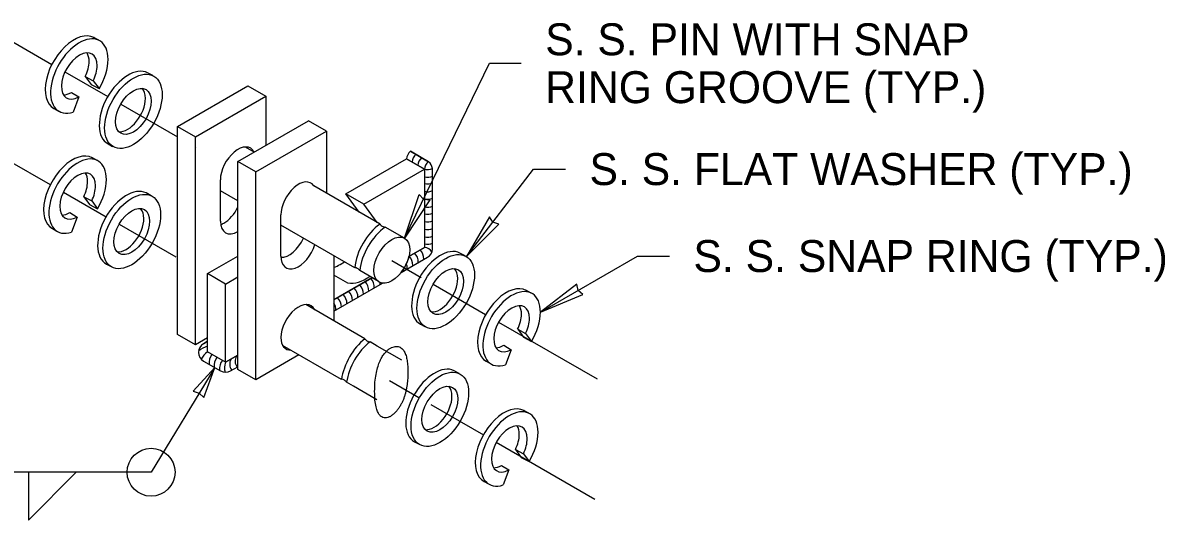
# Model space of a CAD drawing. Extents: x 99862 to 112891, y 95370 to 105076.
# Drawn here: x 101750 to 102323, y 104490 to 104740 of the extents above; entities that cross this region are included whole.
import ezdxf

# ---------------------------------------------------------------- set-up
doc = ezdxf.new("R2010")
doc.units = 0
for name, color, linetype in [('Level 15', 7, 'Continuous'), ('Level 20', 7, 'Continuous'), ('Level 7', 7, 'Continuous'), ('Level 8', 7, 'Continuous')]:
    doc.layers.add(name, color=color, linetype=linetype)

msp = doc.modelspace()

# ---------------------------------------------------------------- linework, layer by layer
at = {"layer": 'Level 15'}
for p, q in [((101743.24, 104731.17), (101764.8, 104718.73)), ((101771.33, 104714.96), (101792.78, 104702.59)), ((101941.54, 104631.62), (101984.05, 104719.3)), ((101984.05, 104719.3), (102000.05, 104719.3)), ((101799.28, 104698.83), (101827.68, 104682.45)), ((101836.69, 104677.25), (101836.95, 104677.1)), ((101742.43, 104670.96), (101763.99, 104658.52)), ((101972.63, 104622.37), (102006.26, 104666.25)), ((102006.26, 104666.25), (102022.26, 104666.25)), ((101770.53, 104654.75), (101791.97, 104642.38)), ((101798.48, 104638.62), (101826.87, 104622.24)), ((102009.65, 104594.55), (102058.36, 104622.68)), ((102058.36, 104622.68), (102074.36, 104622.68)), ((101935.1, 104620.47), (101949.9, 104611.93)), ((101955.84, 104608.51), (101982.19, 104593.31)), ((101988.7, 104589.55), (102038.07, 104561.07)), ((101846.48, 104566.78), (101814.49, 104514.33)), ((101933.96, 104560.25), (101948.76, 104551.72)), ((101954.69, 104548.29), (101981.05, 104533.09)), ((101987.55, 104529.33), (102036.92, 104500.85)), ((101814.49, 104514.33), (101691.48, 104514.33)), ((101753, 104514.33), (101753, 104490.33)), ((101753, 104490.33), (101777, 104514.33))]:
    msp.add_line(p, q, dxfattribs=at)
for points in [[(101941.54, 104631.62), (101948.81, 104653.46), (101951.04, 104651.21), (101954.18, 104650.86)], [(101972.63, 104622.37), (101988.89, 104638.67), (101985.88, 104639.65), (101984.15, 104642.3)], [(102009.65, 104594.55), (102030.91, 104603.38), (102028.51, 104605.44), (102027.93, 104608.55)], [(101846.48, 104566.78), (101835.66, 104554.96), (101838.67, 104553.97), (101840.93, 104551.75)]]:
    msp.add_lwpolyline(points, close=True, dxfattribs=at)
msp.add_circle((101814.49, 104514.33), 12, dxfattribs=at)
at = {"layer": 'Level 7'}
for p, q in [((101788.24, 104730.81), (101785.66, 104732.25)), ((101815.36, 104713.09), (101812.77, 104714.53)), ((101781.53, 104712.64), (101784.44, 104708.67)), ((101781.53, 104712.64), (101785.53, 104710.52)), ((101784.44, 104708.67), (101788.44, 104706.56)), ((101785.53, 104710.52), (101788.44, 104706.56)), ((101774.53, 104704.67), (101778.22, 104702.39)), ((101778.22, 104702.39), (101775.41, 104694.85)), ((101827.68, 104687.61), (101863.03, 104708.02)), ((101836.69, 104682.41), (101872.04, 104702.82)), ((101863.03, 104708.02), (101872.04, 104702.82)), ((101872.04, 104702.82), (101872.04, 104678.2)), ((101765.82, 104696.61), (101768.11, 104695.35)), ((101827.68, 104687.61), (101836.69, 104682.41)), ((101827.68, 104583.41), (101827.68, 104687.61)), ((101858.01, 104670.1), (101893.37, 104690.51)), ((101867.02, 104664.9), (101902.37, 104685.31)), ((101902.37, 104685.31), (101893.37, 104690.51)), ((101902.37, 104685.31), (101902.37, 104654.24)), ((101836.69, 104578.21), (101836.69, 104682.41)), ((101792.93, 104678.89), (101795.22, 104677.63)), ((101866.15, 104674.8), (101861.79, 104677.32)), ((101787.44, 104670.6), (101784.85, 104672.04)), ((101867.02, 104664.9), (101858.01, 104670.1)), ((101858.01, 104565.9), (101858.01, 104670.1)), ((101912.1, 104653.83), (101942.58, 104671.43)), ((101951.58, 104666.23), (101942.58, 104671.43)), ((101867.02, 104560.7), (101867.02, 104664.9)), ((101921.1, 104648.63), (101951.58, 104666.23)), ((101951.58, 104666.23), (101951.58, 104627.03)), ((101849.25, 104640.09), (101849.25, 104660.81)), ((101929.29, 104638.7), (101896.12, 104657.85)), ((101780.72, 104652.43), (101783.64, 104648.46)), ((101780.72, 104652.43), (101784.72, 104650.31)), ((101814.55, 104652.88), (101811.96, 104654.32)), ((101858.01, 104650.3), (101849.25, 104655.36)), ((101918.86, 104644.73), (101912.1, 104653.83)), ((101921.1, 104648.63), (101912.1, 104653.83)), ((101783.64, 104648.46), (101787.63, 104646.34)), ((101784.72, 104650.31), (101787.63, 104646.34)), ((101927.88, 104639.51), (101921.1, 104648.63)), ((101773.73, 104644.46), (101777.41, 104642.18)), ((101777.41, 104642.18), (101774.61, 104634.64)), ((101879.58, 104622.57), (101879.58, 104643.3)), ((101765.01, 104636.4), (101767.31, 104635.14)), ((101916.55, 104616.83), (101879.58, 104638.18)), ((101941.54, 104631.63), (101931.88, 104637.21)), ((101842.85, 104613.85), (101858.01, 104622.6)), ((101906.1, 104622.87), (101906.1, 104590.18)), ((101943.76, 104622.51), (101951.58, 104627.03)), ((101971.91, 104622.76), (101969.33, 104624.2)), ((101792.12, 104618.68), (101794.42, 104617.42)), ((101909.32, 104618.5), (101911.49, 104619.76)), ((101842.85, 104574.65), (101842.85, 104613.85)), ((101851.85, 104608.65), (101842.85, 104613.85)), ((101851.85, 104608.65), (101858.01, 104612.2)), ((101913.04, 104609.17), (101906.1, 104613.18)), ((101906.1, 104600.77), (101925.24, 104611.82)), ((101928.31, 104610.04), (101919.1, 104615.36)), ((101851.85, 104569.45), (101851.85, 104608.65)), ((102004.96, 104604.14), (102002.37, 104605.57)), ((101921.69, 104581.18), (101892, 104598.32)), ((101949.49, 104588.56), (101951.78, 104587.3)), ((101836.69, 104578.21), (101827.68, 104583.41)), ((101998.25, 104585.96), (102001.16, 104582)), ((101998.25, 104585.96), (102002.24, 104583.85)), ((102002.24, 104583.85), (102005.16, 104579.88)), ((101842.85, 104581.76), (101836.69, 104578.21)), ((101909.93, 104560.88), (101880.45, 104577.9)), ((101927.89, 104577.6), (101924.27, 104579.69)), ((101940.13, 104570.54), (101927.89, 104577.6)), ((101991.25, 104578), (101994.93, 104575.72)), ((102001.16, 104582), (102005.16, 104579.88)), ((101851.85, 104569.45), (101842.85, 104574.65)), ((101851.85, 104569.45), (101858.01, 104573.01)), ((101888.62, 104573.17), (101867.02, 104560.7)), ((101994.93, 104575.72), (101992.13, 104568.18)), ((101867.02, 104560.7), (101858.01, 104565.9)), ((101969, 104563.79), (101966.41, 104565.22)), ((101982.53, 104569.94), (101984.83, 104568.68)), ((101915.94, 104557.41), (101912.48, 104559.41)), ((101927.68, 104550.63), (101915.94, 104557.41)), ((102003.82, 104543.92), (102001.23, 104545.36)), ((101946.57, 104529.59), (101948.86, 104528.33)), ((101997.1, 104525.74), (102000.01, 104521.78)), ((101997.1, 104525.74), (102001.1, 104523.63)), ((102000.01, 104521.78), (102004.01, 104519.66)), ((102001.1, 104523.63), (102004.01, 104519.66)), ((101990.11, 104517.78), (101993.79, 104515.5)), ((101993.79, 104515.5), (101990.99, 104507.96)), ((101981.39, 104509.72), (101983.68, 104508.46))]:
    msp.add_line(p, q, dxfattribs=at)
for centre, major_axis, ratio, start_param, end_param in [((101775.84, 104714.38), (10.2, 17.67), 0.57735, 6.163864, 9.44206), ((101778.51, 104712.9), (10.2, 17.67), 0.57735, 5.497787, 9.994128), ((101778.51, 104712.9), (6.34, 10.98), 0.57735, 5.497787, 10.177688), ((101774.5, 104715.01), (6.34, 10.98), 0.57735, 4.827845, 5.497787), ((101774.5, 104715.01), (6.34, 10.98), 0.57735, 5.497787, 5.991841), ((101778.51, 104712.9), (10.2, 17.67), 0.57735, 4.686514, 5.497787), ((101778.51, 104712.9), (6.34, 10.98), 0.57735, 4.826963, 5.497787), ((101802.95, 104696.66), (10.2, 17.67), 0.57735, 0.036728, 3.158875), ((101774.5, 104715.01), (6.34, 10.98), 0.57735, 3.478267, 3.930251), ((101802.72, 104696.53), (6.34, 10.98), 0.57735, 5.497787, 6.114666), ((101802.72, 104696.53), (6.34, 10.98), 0.57735, 3.412792, 5.497787), ((101775.03, 104654.17), (10.2, 17.67), 0.57735, 6.163864, 9.44206), ((101858.08, 104665.91), (6.25, 10.83), 0.57735, 5.924907, 8.63938), ((101777.7, 104652.69), (10.2, 17.67), 0.57735, 5.497787, 9.994128), ((101777.7, 104652.69), (6.34, 10.98), 0.57735, 5.497787, 10.177688), ((101773.7, 104654.79), (6.34, 10.98), 0.57735, 5.497787, 5.991841), ((101773.7, 104654.79), (6.34, 10.98), 0.57735, 4.827845, 5.497787), ((101777.7, 104652.69), (6.34, 10.98), 0.57735, 4.826963, 5.497787), ((101802.14, 104636.44), (10.2, 17.67), 0.57735, 0.036728, 3.158875), ((101777.7, 104652.69), (10.2, 17.67), 0.57735, 4.686514, 5.497787), ((101888.42, 104648.4), (-6.25, -10.83), 0.57735, 2.868315, 5.497787), ((101801.91, 104636.32), (6.34, 10.98), 0.57735, 5.497787, 6.114666), ((101851.01, 104649.39), (6.25, 10.83), 0.57735, 3.918713, 4.842037), ((101773.7, 104654.79), (6.34, 10.98), 0.57735, 3.478267, 3.930251), ((101801.91, 104636.32), (6.34, 10.98), 0.57735, 3.412792, 5.497787), ((101858.08, 104645.19), (6.25, 10.83), 0.57735, 2.356194, 3.918713), ((101851.01, 104649.39), (6.25, 10.83), 0.57735, 3.741522, 3.918713), ((101930.87, 104623.05), (10.2, 17.67), 0.57735, 0.895049, 2.233314), ((101933.41, 104621.53), (10.2, 17.67), 0.57735, 0.891866, 2.230172), ((101930.58, 104637.95), (1.29, -0.75), 0.229667, 3.141593, 6.096097), ((101888.42, 104627.68), (6.25, 10.83), 0.57735, 2.356194, 5.095834), ((101883.78, 104633.47), (6.25, 10.83), 0.57735, 3.432988, 4.871182), ((101959.51, 104606.33), (10.2, 17.67), 0.57735, 0.036728, 3.158875), ((101909.32, 104668.8), (-9.15, -52.25), 0.457456, 0.239539, 0.365772), ((101917.84, 104616.07), (1.28, -0.76), 0.229667, 0.326419, 3.141593), ((101922.05, 104661.45), (-9.15, -52.25), 0.457456, 0.006259, 0.445323), ((101959.28, 104606.2), (6.34, 10.98), 0.57735, 3.412792, 5.497787), ((101959.28, 104606.2), (6.34, 10.98), 0.57735, 5.497787, 6.114666), ((101992.56, 104587.7), (10.2, 17.67), 0.57735, 6.163864, 9.44206), ((101995.23, 104586.23), (10.2, 17.67), 0.57735, 5.497787, 9.994128), ((101995.23, 104586.23), (6.34, 10.98), 0.57735, 5.497787, 10.177688), ((101888.42, 104586.92), (-6.25, -10.83), 0.57735, 2.771879, 5.497787), ((101991.22, 104588.33), (6.34, 10.98), 0.57735, 5.497787, 5.991841), ((101995.23, 104586.23), (10.2, 17.67), 0.57735, 4.686514, 5.497787), ((101991.22, 104588.33), (6.34, 10.98), 0.57735, 4.827845, 5.497787), ((101995.23, 104586.23), (6.34, 10.98), 0.57735, 4.826963, 5.497787), ((101888.42, 104586.92), (-6.25, -10.83), 0.57735, 5.497787, 6.617535), ((101924.14, 104566.19), (10.2, 17.67), 0.57735, 0.956158, 2.18156), ((101926.68, 104564.66), (10.2, 17.67), 0.57735, 0.953119, 2.178536), ((101922.98, 104580.44), (1.29, -0.75), 0.229667, 3.141593, 6.096097), ((101991.22, 104588.33), (6.34, 10.98), 0.57735, 3.478267, 3.930251), ((101956.59, 104547.35), (10.2, 17.67), 0.57735, 0.036728, 3.158875), ((101911.2, 104560.17), (1.28, -0.76), 0.229667, 6.283185, 9.424778), ((101956.36, 104547.22), (6.34, 10.98), 0.57735, 5.497787, 6.114666), ((101956.36, 104547.22), (6.34, 10.98), 0.57735, 3.412792, 5.497787), ((101991.41, 104527.48), (10.2, 17.67), 0.57735, 6.163864, 9.44206), ((101994.08, 104526.01), (10.2, 17.67), 0.57735, 5.497787, 9.994128), ((101994.08, 104526.01), (6.34, 10.98), 0.57735, 5.497787, 10.177688), ((101990.08, 104528.11), (6.34, 10.98), 0.57735, 5.497787, 5.991841), ((101990.08, 104528.11), (6.34, 10.98), 0.57735, 4.827845, 5.497787), ((101994.08, 104526.01), (6.34, 10.98), 0.57735, 4.826963, 5.497787), ((101994.08, 104526.01), (10.2, 17.67), 0.57735, 4.686514, 5.497787), ((101990.08, 104528.11), (6.34, 10.98), 0.57735, 3.478267, 3.930251)]:
    msp.add_ellipse(centre, major_axis=major_axis, ratio=ratio, start_param=start_param, end_param=end_param, dxfattribs=at)
for centre, major_axis in [((101805.62, 104695.18), (10.2, 17.67)), ((101805.62, 104695.18), (6.34, 10.98)), ((101804.81, 104634.97), (10.2, 17.67)), ((101804.81, 104634.97), (6.34, 10.98)), ((101935.2, 104620.64), (6.34, 10.98)), ((101962.18, 104604.85), (10.2, 17.67)), ((101962.18, 104604.85), (6.34, 10.98)), ((101959.26, 104545.88), (10.2, 17.67)), ((101959.26, 104545.88), (6.34, 10.98))]:
    msp.add_ellipse(centre, major_axis=major_axis, ratio=0.57735, dxfattribs=at)
msp.add_open_spline([(101926.55, 104554.86), (101926.55, 104535.27), (101943.52, 104545.06), (101943.52, 104564.66), (101943.52, 104584.26), (101926.55, 104574.46), (101926.55, 104554.86)], degree=4, dxfattribs=at)
at = {"layer": 'Level 8'}
for p, q in [((101944.48, 104675.21), (101953.58, 104669.88)), ((101944.48, 104675.21), (101953.58, 104669.88)), ((101955.55, 104626.13), (101955.55, 104666.62)), ((101955.55, 104626.13), (101955.55, 104666.62)), ((101939.85, 104614.49), (101953.06, 104622.11)), ((101939.85, 104614.49), (101953.06, 104622.11)), ((101906.1, 104595), (101930.54, 104609.11)), ((101906.1, 104595), (101930.54, 104609.11)), ((101840.76, 104578.74), (101842.85, 104579.94)), ((101840.76, 104578.74), (101842.85, 104579.94)), ((101840.76, 104570.08), (101849.35, 104565.12)), ((101840.76, 104570.08), (101849.35, 104565.12)), ((101854.35, 104565.12), (101858.01, 104567.24)), ((101854.35, 104565.12), (101858.01, 104567.24))]:
    msp.add_line(p, q, dxfattribs=at)
for points in [[(101953.58, 104669.88), (101944.48, 104675.21)], [(101942.58, 104671.43), (101951.58, 104666.23), (101951.58, 104627.03), (101943.76, 104622.51)], [(101955.55, 104626.13), (101955.54, 104666.63)], [(101939.85, 104614.49), (101953.06, 104622.11)], [(101928.31, 104610.04), (101925.23, 104611.82), (101925.23, 104611.82), (101906.1, 104600.77), (101906.1, 104595), (101930.54, 104609.11)], [(101858.01, 104567.24), (101858.01, 104573.01), (101851.85, 104569.45), (101842.85, 104574.65), (101842.85, 104579.94), (101840.76, 104578.74)], [(101840.76, 104570.08), (101849.35, 104565.12)], [(101854.35, 104565.12), (101858.01, 104567.24)]]:
    msp.add_lwpolyline(points, dxfattribs=at)
for centre, radius, start, end in [((101950.6, 104665.87), 5, 8.7253, 53.3723), ((101950.6, 104665.87), 5, 8.7253, 53.3723), ((101950.6, 104665.87), 5, 8.7253, 53.3723), ((101939.31, 104618.02), 6.38, 359.3272, 45.1315), ((101942.06, 104619.64), 6.38, 359.3272, 44.8966), ((101944.82, 104621.26), 6.38, 359.3272, 44.662), ((101950.75, 104621.49), 5.61, 36.1365, 81.4761), ((101950.56, 104626.44), 5, 300, 356.4877), ((101950.56, 104626.44), 5, 300, 356.4877), ((101950.56, 104626.44), 5, 300, 356.4877), ((101936.55, 104616.4), 6.38, 359.3272, 21.9535), ((101919.95, 104607.15), 6.38, 355.6581, 42.6639), ((101909.06, 104600.44), 6.38, 359.3272, 45.8564), ((101911.82, 104602.06), 6.38, 359.3272, 45.8564), ((101914.53, 104603.76), 6.38, 358.1206, 45.8564), ((101917.24, 104605.46), 6.38, 356.898, 43.7231), ((101922.95, 104608.49), 6.38, 359.3272, 8.7653), ((101903.54, 104597.19), 6.38, 359.3272, 45.8564), ((101906.3, 104598.82), 6.38, 359.3272, 45.8564), ((101900.78, 104595.57), 6.38, 359.3272, 33.6619), ((101843.26, 104574.41), 5, 120, 240), ((101843.26, 104574.41), 5, 120, 240), ((101843.26, 104574.41), 5, 120, 240), ((101845.24, 104567.59), 10.17, 103.5929, 132.9563), ((101847.59, 104567.35), 8.71, 122.9788, 155.5782), ((101849.91, 104569.26), 6.38, 141.1605, 187.2593), ((101852.41, 104567.79), 6.38, 141.1605, 187.0152), ((101858.77, 104568.5), 4.87, 148.4379, 218.45), ((101861.47, 104570.09), 4.87, 149.0861, 218.7654), ((101855.17, 104566.33), 6.38, 140.5422, 186.8172), ((101851.85, 104569.45), 5, 240, 300), ((101851.85, 104569.45), 5, 240, 300), ((101851.85, 104569.45), 5, 240, 300), ((101858.24, 104566.56), 7.01, 155.6576, 197.4441)]:
    msp.add_arc(centre, radius, start, end, dxfattribs=at)
for centre, major_axis, start_param, end_param in [((101945.07, 104672.77), (1.78, 3.03), 1.029182, 2.328763), ((101945.07, 104672.77), (1.78, 3.03), 1.029182, 2.328763), ((101945.07, 104672.77), (1.78, 3.03), 1.029182, 2.328763), ((101947.83, 104671.23), (1.78, 3.03), 1.052269, 2.328763), ((101950.73, 104669.53), (1.78, 3.03), 1.052269, 2.328763), ((101954.08, 104667.57), (1.78, 3.03), 1.052269, 2.331147), ((101953.13, 104668.1), (-3.52, 0), 1.05469, 2.331147), ((101953.13, 104664.23), (-3.52, 0), 1.114434, 2.328763), ((101953.13, 104660.86), (-3.52, 0), 1.114434, 2.328763), ((101953.13, 104656.95), (-3.52, 0), 1.114434, 2.328763), ((101953.13, 104653.15), (-3.52, 0), 1.114434, 2.328763), ((101953.13, 104649.18), (-3.52, 0), 1.114434, 2.328763), ((101953.13, 104645.63), (-3.52, 0), 1.114434, 2.328763), ((101953.13, 104641.78), (-3.52, 0), 1.114434, 2.328763), ((101953.13, 104637.96), (-3.52, 0), 1.114434, 2.328763), ((101953.13, 104634.11), (-3.52, 0), 1.114434, 2.328763), ((101953.13, 104630.56), (-3.52, 0), 1.114434, 2.328763), ((101935.2, 104620.64), (6.34, 10.98), 4.473093, 5.196638), ((101935.2, 104620.64), (6.34, 10.98), 3.050909, 3.380888)]:
    msp.add_ellipse(centre, major_axis=major_axis, ratio=0.57735, start_param=start_param, end_param=end_param, dxfattribs=at)

# ---------------------------------------------------------------- texts
at = {"layer": 'Level 20'}
for s, p in [('S. S. PIN WITH SNAP', (102012.05, 104723.3)), ('RING GROOVE (TYP.)', (102012.05, 104699.3)), ('S. S. FLAT WASHER (TYP.)', (102034.26, 104658.25)), ('S. S. SNAP RING (TYP.)', (102086.36, 104614.68))]:
    msp.add_text(s, height=16, dxfattribs=at).set_placement(p)

doc.saveas('drawing.dxf')
